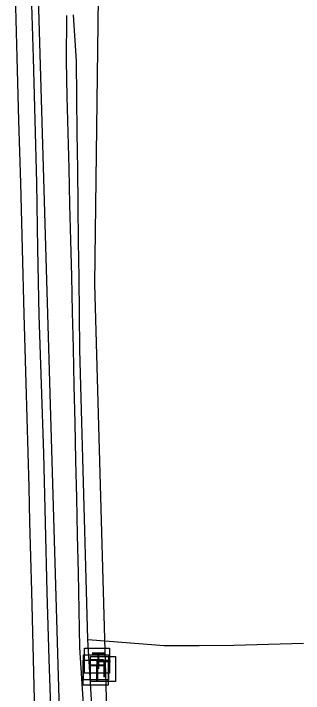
# Model space of a CAD drawing. Extents: x 1930288 to 1941089, y 588389 to 611475.
# Drawn here: x 1930894.3 to 1930998.7, y 597559.1 to 597803.8 of the extents above; entities that cross this region are included whole.
import ezdxf

# ---------------------------------------------------------------- set-up
doc = ezdxf.new("R2010")
doc.units = 0
for name, color, linetype in [('S_BASELINE', 7, 'Continuous'), ('S_DITCHLINE', 7, 'Continuous'), ('S_EDGE_PAVEMENT', 7, 'Continuous'), ('S_SANITARY_SEWER', 7, 'Continuous'), ('S_SHOULDER', 7, 'Continuous'), ('S_TELEPHONE_UTILITIES', 7, 'Continuous'), ('S_UTL_PT_SYM', 7, 'Continuous')]:
    doc.layers.add(name, color=color, linetype=linetype)

msp = doc.modelspace()

# ---------------------------------------------------------------- linework, layer by layer
at = {"layer": 'S_BASELINE'}
msp.add_line((1930922.05, 597172.86), (1930894.27, 598110.49), dxfattribs=at)
at = {"layer": 'S_DITCHLINE'}
for points in [[(1930919.53, 597553.23), (1930918.17, 597575.56), (1930917.88, 597589.04), (1930917.59, 597602.51), (1930917.3, 597615.99), (1930917.01, 597629.46), (1930916.72, 597642.94), (1930916.43, 597656.41), (1930916.14, 597669.89), (1930915.85, 597683.36), (1930915.54, 597696.29), (1930915.22, 597709.22), (1930914.9, 597722.15), (1930914.58, 597735.08), (1930914.26, 597748.01), (1930913.94, 597760.94), (1930913.62, 597773.87), (1930913.3, 597786.79), (1930913.44, 597803.09)], [(1930922.44, 597554.8), (1930921.05, 597578.52), (1930920.69, 597591.56), (1930920.33, 597604.6), (1930919.97, 597617.64), (1930919.61, 597630.68), (1930919.25, 597643.72), (1930918.89, 597656.76), (1930918.53, 597669.8), (1930918.18, 597682.84), (1930918.01, 597695.82), (1930917.85, 597708.79), (1930917.69, 597721.77), (1930917.53, 597734.74), (1930917.37, 597747.72), (1930917.21, 597760.69), (1930917.05, 597773.67), (1930916.89, 597786.64), (1930915.85, 597803.31)], [(1930921.05, 597578.52), (1930934.8, 597577.43), (1930948.55, 597576.34), (1930961.07, 597576.37), (1930973.59, 597576.4), (1930986.13, 597576.76), (1930998.67, 597577.13)]]:
    msp.add_lwpolyline(points, dxfattribs=at)
at = {"layer": 'S_EDGE_PAVEMENT'}
msp.add_lwpolyline([(1930894.81, 597810.89), (1930895.42, 597787.94), (1930896.08, 597765.33), (1930896.73, 597742.72), (1930897.37, 597719.14), (1930898.01, 597695.55), (1930898.7, 597670.7), (1930899.39, 597645.85), (1930899.71, 597633.32), (1930900.04, 597620.8), (1930900.36, 597608.28), (1930900.69, 597595.75), (1930901.33, 597571.38), (1930901.97, 597547)], dxfattribs=at)
at = {"layer": 'S_SANITARY_SEWER'}
for p, q in [((1930923.55, 597706.51), (1930927.31, 598000.04)), ((1930939.56, 597140.44), (1930923.55, 597706.51))]:
    msp.add_line(p, q, dxfattribs=at)
at = {"layer": 'S_SHOULDER'}
msp.add_lwpolyline([(1930900.65, 597810.97), (1930901.33, 597787.88), (1930901.9, 597765.38), (1930902.48, 597742.88), (1930902.94, 597719.08), (1930903.41, 597695.28), (1930904.2, 597670.36), (1930905, 597645.43), (1930905.63, 597620.45), (1930906.26, 597595.47), (1930907.01, 597571.39), (1930907.77, 597547.31)], dxfattribs=at)
at = {"layer": 'S_TELEPHONE_UTILITIES'}
for points in [[(1930919.8, 597566.35), (1930919.8, 597575.35), (1930928.8, 597575.35), (1930928.8, 597566.35)], [(1930919.42, 597563.91), (1930919.42, 597572.91), (1930928.42, 597572.91), (1930928.42, 597563.91)], [(1930921.99, 597563.38), (1930921.99, 597572.38), (1930930.99, 597572.38), (1930930.99, 597563.38)], [(1930919.37, 597561.99), (1930919.37, 597570.99), (1930928.37, 597570.99), (1930928.37, 597561.99)]]:
    msp.add_lwpolyline(points, close=True, dxfattribs=at)
at = {"layer": 'S_UTL_PT_SYM'}
msp.add_lwpolyline([(1930923.55, 597706.51), (1930923.55, 597706.56), (1930923.55, 597706.51), (1930923.5, 597706.51), (1930923.55, 597706.51), (1930923.55, 597706.46), (1930923.55, 597706.51), (1930923.6, 597706.51)], dxfattribs=at)

# ---------------------------------------------------------------- texts
at = {"layer": 'S_TELEPHONE_UTILITIES'}
for p in [(1930922.37, 597567.85), (1930921.93, 597563.49), (1930921.99, 597565.41), (1930924.56, 597564.88)]:
    msp.add_text('T', height=6, rotation=360, dxfattribs=at).set_placement(p)

doc.saveas('drawing.dxf')
